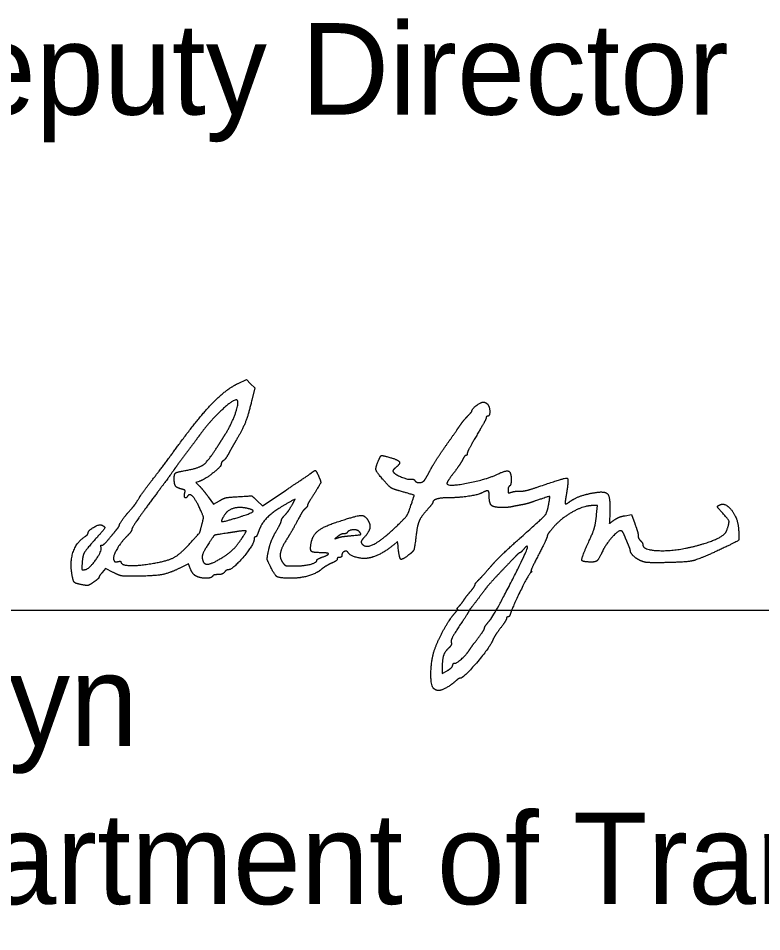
# Model space of a CAD drawing. Extents: x 0 to 68.9, y -26.1 to 22.
# Drawn here: x 25.975 to 27.114, y 8.446 to 9.844 of the extents above; entities that cross this region are included whole.
import ezdxf

# ---------------------------------------------------------------- set-up
doc = ezdxf.new("R2010")
doc.units = 0
doc.layers.add('SH_Data', color=7, linetype='Continuous')
doc.layers.add('SH_Text', color=7, linetype='Continuous')

msp = doc.modelspace()

# ---------------------------------------------------------------- linework, layer by layer
at = {"layer": 'SH_Data'}
msp.add_line((24.827, 8.9384), (28.327, 8.9384), dxfattribs=at)
at = {"layer": 'SH_Text'}
for points in [[(26.3123, 9.2855), (26.3249, 9.2913), (26.3313, 9.285), (26.3376, 9.2786), (26.3332, 9.2599)], [(26.2524, 9.1355), (26.2473, 9.1339), (26.2525, 9.1288)], [(26.3413, 9.1058), (26.3495, 9.0982), (26.3857, 9.1223)], [(26.2662, 9.1121), (26.2747, 9.1006), (26.2835, 9.1058)], [(26.3952, 9.1005), (26.3997, 9.1085), (26.3941, 9.1055)], [(26.8611, 9.0846), (26.8625, 9.0984), (26.8547, 9.0984)], [(26.9049, 9.083), (26.9146, 9.0846), (26.9196, 9.071)], [(26.557, 9.0369), (26.5563, 9.0437), (26.5504, 9.0386)], [(26.2393, 9.0013), (26.236, 9.0093), (26.2221, 9.0024)], [(26.1207, 8.9962), (26.1092, 9.002), (26.1042, 8.9962)], [(26.6247, 8.8507), (26.6247, 8.8414), (26.6322, 8.8457)]]:
    msp.add_lwpolyline(points, dxfattribs=at)
for points in [[(26.2227, 9.1936), (26.2524, 9.2342), (26.2942, 9.2771), (26.3123, 9.2855)], [(26.3108, 9.2597), (26.3072, 9.2633), (26.2686, 9.2276), (26.2532, 9.2063)], [(26.2925, 9.2076), (26.302, 9.2225), (26.3139, 9.2566), (26.3108, 9.2597)], [(26.3332, 9.2599), (26.3282, 9.2388), (26.3191, 9.2152), (26.3096, 9.1992)], [(26.6703, 9.2436), (26.6703, 9.2464), (26.6835, 9.2567), (26.6872, 9.2568)], [(26.6872, 9.2568), (26.6893, 9.2568), (26.6922, 9.2555), (26.6938, 9.254)], [(26.6637, 9.2355), (26.6673, 9.2391), (26.6703, 9.2427), (26.6703, 9.2436)], [(26.6938, 9.254), (26.6973, 9.2505), (26.6977, 9.2352), (26.6943, 9.2352)], [(26.6499, 9.2182), (26.6539, 9.2241), (26.6601, 9.2318), (26.6637, 9.2355)], [(26.6919, 9.2327), (26.6919, 9.2313), (26.6854, 9.2192), (26.6775, 9.2059)], [(26.6943, 9.2352), (26.693, 9.2352), (26.6919, 9.2341), (26.6919, 9.2327)], [(26.6283, 9.1872), (26.6362, 9.1985), (26.646, 9.2124), (26.6499, 9.2182)], [(26.2532, 9.2063), (26.2496, 9.2014), (26.2402, 9.1887), (26.2323, 9.1782)], [(26.282, 9.191), (26.2853, 9.1962), (26.29, 9.2037), (26.2925, 9.2076)], [(26.6775, 9.2059), (26.6696, 9.1925), (26.6631, 9.1801), (26.6631, 9.1784)], [(26.1826, 9.1402), (26.1914, 9.1515), (26.2095, 9.1756), (26.2227, 9.1936)], [(26.2322, 9.1523), (26.2528, 9.156), (26.2668, 9.167), (26.282, 9.191)], [(26.3096, 9.1992), (26.3061, 9.1933), (26.3009, 9.1841), (26.2981, 9.1788)], [(26.6069, 9.1536), (26.6107, 9.1609), (26.6204, 9.176), (26.6283, 9.1872)], [(26.2323, 9.1782), (26.2244, 9.1677), (26.2163, 9.1567), (26.2143, 9.1538)], [(26.2981, 9.1788), (26.2952, 9.1736), (26.2914, 9.1684), (26.2896, 9.1673)], [(26.5263, 9.1655), (26.53, 9.1745), (26.5331, 9.1756), (26.5458, 9.1718)], [(26.6611, 9.1752), (26.66, 9.1752), (26.6577, 9.1723), (26.6559, 9.1686)], [(26.6631, 9.1784), (26.6631, 9.1766), (26.6622, 9.1752), (26.6611, 9.1752)], [(26.2863, 9.1619), (26.2863, 9.1581), (26.2605, 9.1381), (26.2524, 9.1355)], [(26.2896, 9.1673), (26.2878, 9.1663), (26.2863, 9.1638), (26.2863, 9.1619)], [(26.5361, 9.136), (26.5245, 9.1491), (26.5223, 9.1559), (26.5263, 9.1655)], [(26.5458, 9.1718), (26.5578, 9.1683), (26.5607, 9.1621), (26.553, 9.1562)], [(26.6559, 9.1686), (26.6541, 9.165), (26.6479, 9.1559), (26.6423, 9.1484)], [(26.2143, 9.1538), (26.2123, 9.1508), (26.197, 9.1299), (26.1802, 9.1072)], [(26.2143, 9.1402), (26.2143, 9.147), (26.2184, 9.1498), (26.2322, 9.1523)], [(26.3857, 9.1223), (26.4056, 9.1356), (26.4232, 9.1475), (26.4248, 9.1488)], [(26.4248, 9.1488), (26.4294, 9.1526), (26.4317, 9.1517), (26.4347, 9.1451)], [(26.4347, 9.1451), (26.4391, 9.1355), (26.4382, 9.1314), (26.4279, 9.1155)], [(26.553, 9.1562), (26.5503, 9.1541), (26.5488, 9.1513), (26.5498, 9.15)], [(26.5498, 9.15), (26.5524, 9.1462), (26.5724, 9.138), (26.577, 9.1388)], [(26.5977, 9.1374), (26.5989, 9.1391), (26.6031, 9.1464), (26.6069, 9.1536)], [(26.6423, 9.1484), (26.6366, 9.141), (26.6319, 9.1337), (26.6319, 9.1324)], [(26.6319, 9.1324), (26.6319, 9.1271), (26.6915, 9.138), (26.7095, 9.1466)], [(26.7095, 9.1466), (26.7225, 9.1528), (26.7303, 9.1496), (26.7303, 9.1382)], [(26.161, 9.1108), (26.164, 9.1156), (26.1737, 9.1288), (26.1826, 9.1402)], [(26.2253, 9.1238), (26.2181, 9.1256), (26.2143, 9.1313), (26.2143, 9.1402)], [(26.5595, 9.1209), (26.5488, 9.124), (26.5438, 9.1272), (26.5361, 9.136)], [(26.577, 9.1388), (26.5792, 9.1392), (26.5818, 9.1383), (26.5826, 9.137)], [(26.5826, 9.137), (26.5848, 9.1335), (26.5948, 9.1338), (26.5977, 9.1374)], [(26.7303, 9.1382), (26.7303, 9.1337), (26.7292, 9.1293), (26.7279, 9.1284)], [(26.7727, 9.1275), (26.813, 9.1414), (26.8189, 9.1398), (26.8148, 9.1159)], [(26.2304, 9.1175), (26.2313, 9.1211), (26.2301, 9.1226), (26.2253, 9.1238)], [(26.2347, 9.1128), (26.2323, 9.1089), (26.2291, 9.1124), (26.2304, 9.1175)], [(26.2525, 9.1288), (26.2553, 9.126), (26.2615, 9.1185), (26.2662, 9.1121)], [(26.5763, 9.0972), (26.582, 9.114), (26.5816, 9.1146), (26.5595, 9.1209)], [(26.6853, 9.1178), (26.6797, 9.1148), (26.6495, 9.1104), (26.6346, 9.1104)], [(26.6967, 9.1131), (26.6967, 9.1204), (26.693, 9.1219), (26.6853, 9.1178)], [(26.7279, 9.1284), (26.7266, 9.1276), (26.7255, 9.1248), (26.7255, 9.1221)], [(26.7255, 9.1221), (26.7255, 9.1182), (26.7265, 9.1176), (26.7309, 9.119)], [(26.7309, 9.119), (26.7339, 9.12), (26.7397, 9.1206), (26.7439, 9.1205)], [(26.7439, 9.1205), (26.748, 9.1203), (26.761, 9.1235), (26.7727, 9.1275)], [(26.8208, 9.105), (26.828, 9.1101), (26.8463, 9.1164), (26.8599, 9.1186)], [(26.8599, 9.1186), (26.8746, 9.1209), (26.8822, 9.1104), (26.8814, 9.0892)], [(26.1447, 9.0889), (26.1513, 9.0962), (26.1556, 9.102), (26.161, 9.1108)], [(26.1802, 9.1072), (26.1634, 9.0846), (26.1496, 9.0644), (26.1495, 9.0624)], [(26.2535, 9.0942), (26.2473, 9.1078), (26.2376, 9.1175), (26.2347, 9.1128)], [(26.2835, 9.1058), (26.29, 9.1097), (26.2976, 9.1114), (26.3127, 9.1122)], [(26.3127, 9.1122), (26.333, 9.1134), (26.3332, 9.1134), (26.3413, 9.1058)], [(26.3941, 9.1055), (26.3707, 9.093), (26.348, 9.0723), (26.3439, 9.0599)], [(26.4279, 9.1155), (26.4226, 9.1074), (26.4183, 9.0998), (26.4183, 9.0987)], [(26.6103, 9.1033), (26.6103, 9.1024), (26.6061, 9.097), (26.601, 9.0912)], [(26.6346, 9.1104), (26.6231, 9.1104), (26.6103, 9.1067), (26.6103, 9.1033)], [(26.716, 9.0955), (26.7036, 9.0955), (26.6967, 9.1018), (26.6967, 9.1131)], [(26.7673, 9.1055), (26.7595, 9.1028), (26.7499, 9.1001), (26.7459, 9.0995)], [(26.7879, 9.1009), (26.79, 9.1124), (26.7883, 9.1128), (26.7673, 9.1055)], [(26.8148, 9.1159), (26.8135, 9.1083), (26.8128, 9.1017), (26.8132, 9.1012)], [(26.8132, 9.1012), (26.8137, 9.1007), (26.8171, 9.1024), (26.8208, 9.105)], [(26.1303, 9.0684), (26.1303, 9.0701), (26.1395, 9.0831), (26.1447, 9.0889)], [(26.2568, 9.0696), (26.2593, 9.0795), (26.259, 9.0817), (26.2535, 9.0942)], [(26.3245, 9.0945), (26.3137, 9.0967), (26.2963, 9.0916), (26.2919, 9.085)], [(26.3139, 9.081), (26.3331, 9.0869), (26.3371, 9.092), (26.3245, 9.0945)], [(26.3824, 9.0824), (26.3879, 9.0884), (26.3904, 9.092), (26.3952, 9.1005)], [(26.4148, 9.0937), (26.4128, 9.0921), (26.4097, 9.0879), (26.4079, 9.0844)], [(26.4183, 9.0987), (26.4183, 9.0975), (26.4167, 9.0953), (26.4148, 9.0937)], [(26.558, 9.0699), (26.5684, 9.0799), (26.5726, 9.0861), (26.5763, 9.0972)], [(26.601, 9.0912), (26.5925, 9.0817), (26.5868, 9.0692), (26.5852, 9.0564)], [(26.7327, 9.0969), (26.7294, 9.0961), (26.7219, 9.0955), (26.716, 9.0955)], [(26.7459, 9.0995), (26.742, 9.0988), (26.736, 9.0977), (26.7327, 9.0969)], [(26.7431, 9.0479), (26.7786, 9.0795), (26.7855, 9.0876), (26.7879, 9.1009)], [(26.8547, 9.0984), (26.842, 9.0984), (26.8083, 9.08), (26.7961, 9.0665)], [(26.8814, 9.0892), (26.8808, 9.0708), (26.8806, 9.0711), (26.8884, 9.0766)], [(27.0515, 9.0898), (27.0462, 9.0955), (27.046, 9.0981), (27.0506, 9.0999)], [(27.0506, 9.0999), (27.0592, 9.1032), (27.0776, 9.0783), (27.0786, 9.062)], [(27.0606, 9.0607), (27.0646, 9.0725), (27.0631, 9.0774), (27.0515, 9.0898)], [(26.2919, 9.085), (26.2849, 9.0743), (26.2895, 9.0735), (26.3139, 9.081)], [(26.37, 9.0583), (26.3744, 9.066), (26.3782, 9.0736), (26.3784, 9.0754)], [(26.3784, 9.0754), (26.3787, 9.0771), (26.3805, 9.0803), (26.3824, 9.0824)], [(26.4079, 9.0844), (26.3997, 9.069), (26.392, 9.0552), (26.3858, 9.0455)], [(26.4617, 9.0727), (26.4935, 9.0833), (26.507, 9.0837), (26.512, 9.0742)], [(26.512, 9.0742), (26.5152, 9.0682), (26.5118, 9.0568), (26.5044, 9.0489)], [(26.8464, 9.0368), (26.8554, 9.0567), (26.8595, 9.0699), (26.8611, 9.0846)], [(26.8884, 9.0766), (26.8921, 9.0793), (26.8996, 9.0822), (26.9049, 9.083)], [(26.0823, 9.0564), (26.0824, 9.0602), (26.0991, 9.0701), (26.1029, 9.0687)], [(26.1029, 9.0687), (26.1089, 9.0664), (26.1066, 9.0615), (26.0923, 9.0456)], [(26.1158, 9.0492), (26.1211, 9.0558), (26.1266, 9.0625), (26.1279, 9.0641)], [(26.1279, 9.0641), (26.1292, 9.0657), (26.1303, 9.0677), (26.1303, 9.0684)], [(26.1495, 9.0624), (26.1494, 9.0605), (26.1461, 9.0556), (26.1421, 9.0517)], [(26.2371, 9.0391), (26.2532, 9.0567), (26.2535, 9.0572), (26.2568, 9.0696)], [(26.4241, 9.0416), (26.4262, 9.0529), (26.4424, 9.0663), (26.4617, 9.0727)], [(26.4978, 9.0585), (26.495, 9.0618), (26.4816, 9.061), (26.4793, 9.0574)], [(26.501, 9.041), (26.5064, 9.0324), (26.5331, 9.0459), (26.558, 9.0699)], [(26.7961, 9.0665), (26.7903, 9.06), (26.7855, 9.0534), (26.7855, 9.0519)], [(26.9196, 9.071), (26.9224, 9.0636), (26.9247, 9.0554), (26.9247, 9.0529)], [(27.0118, 9.0364), (27.0354, 9.0427), (27.0584, 9.0541), (27.0606, 9.0607)], [(27.0786, 9.062), (27.0796, 9.0467), (27.0769, 9.0436), (27.0535, 9.0326)], [(26.0575, 8.9948), (26.0545, 9.0133), (26.0653, 9.0433), (26.0777, 9.0511)], [(26.0777, 9.0511), (26.0802, 9.0527), (26.0823, 9.0551), (26.0823, 9.0564)], [(26.1035, 9.0379), (26.1049, 9.0376), (26.1104, 9.0426), (26.1158, 9.0492)], [(26.1421, 9.0517), (26.1323, 9.0421), (26.1199, 9.02), (26.1217, 9.0153)], [(26.2947, 9.0562), (26.2769, 9.0536), (26.2749, 9.0525), (26.2676, 9.0413)], [(26.2872, 9.0185), (26.2984, 9.0255), (26.3094, 9.036), (26.3171, 9.0472)], [(26.3121, 9.0589), (26.3065, 9.058), (26.2987, 9.0568), (26.2947, 9.0562)], [(26.3367, 9.0474), (26.3365, 9.0389), (26.3034, 9), (26.2963, 9)], [(26.3171, 9.0472), (26.3249, 9.0586), (26.324, 9.0607), (26.3121, 9.0589)], [(26.3387, 9.0504), (26.3376, 9.0504), (26.3367, 9.0491), (26.3367, 9.0474)], [(26.3439, 9.0599), (26.3421, 9.0547), (26.3398, 9.0504), (26.3387, 9.0504)], [(26.359, 9.0305), (26.3606, 9.0381), (26.3655, 9.0507), (26.37, 9.0583)], [(26.465, 9.0514), (26.4604, 9.0477), (26.4604, 9.0477), (26.4651, 9.0493)], [(26.4738, 9.0552), (26.4715, 9.0552), (26.4675, 9.0535), (26.465, 9.0514)], [(26.4651, 9.0493), (26.4678, 9.0503), (26.4753, 9.0515), (26.4819, 9.0521)], [(26.4793, 9.0574), (26.4786, 9.0562), (26.4761, 9.0552), (26.4738, 9.0552)], [(26.4819, 9.0521), (26.4986, 9.0536), (26.501, 9.0546), (26.4978, 9.0585)], [(26.5044, 9.0489), (26.5017, 9.046), (26.5001, 9.0424), (26.501, 9.041)], [(26.5852, 9.0564), (26.5823, 9.0339), (26.5806, 9.0284), (26.5749, 9.024)], [(26.699, 9.0052), (26.7062, 9.0136), (26.7261, 9.0328), (26.7431, 9.0479)], [(26.7855, 9.0519), (26.7855, 9.0503), (26.7796, 9.0374), (26.7723, 9.0233)], [(26.8979, 9.06), (26.8936, 9.06), (26.8754, 9.0395), (26.8706, 9.0294)], [(26.9035, 9.0534), (26.902, 9.0571), (26.8995, 9.06), (26.8979, 9.06)], [(26.9094, 9.0393), (26.9077, 9.0434), (26.905, 9.0498), (26.9035, 9.0534)], [(26.9247, 9.0529), (26.9247, 9.0504), (26.9263, 9.0468), (26.9283, 9.0448)], [(26.0923, 9.0456), (26.0786, 9.0304), (26.0736, 9.0203), (26.073, 9.0065)], [(26.0779, 9.0005), (26.0842, 9.0014), (26.1043, 9.0298), (26.1023, 9.035)], [(26.1023, 9.035), (26.1015, 9.037), (26.1021, 9.0383), (26.1035, 9.0379)], [(26.1806, 9.0098), (26.2033, 9.0135), (26.223, 9.0237), (26.2371, 9.0391)], [(26.2676, 9.0413), (26.2594, 9.0286), (26.2562, 9.0188), (26.2585, 9.013)], [(26.3858, 9.0455), (26.3779, 9.0329), (26.3756, 9.0177), (26.3807, 9.0109)], [(26.4377, 9.0264), (26.4261, 9.0264), (26.4221, 9.031), (26.4241, 9.0416)], [(26.5504, 9.0386), (26.5411, 9.0304), (26.521, 9.0198), (26.5119, 9.0181)], [(26.5749, 9.024), (26.5632, 9.0148), (26.5588, 9.0179), (26.557, 9.0369)], [(26.6964, 8.9214), (26.7041, 8.9301), (26.7573, 9.0338), (26.7552, 9.0359)], [(26.7552, 9.0359), (26.7545, 9.0366), (26.7519, 9.0348), (26.7495, 9.0318)], [(26.8537, 9.012), (26.8392, 9.012), (26.8376, 9.0175), (26.8464, 9.0368)], [(26.9128, 9.0297), (26.9127, 9.0308), (26.9112, 9.0351), (26.9094, 9.0393)], [(26.9283, 9.0448), (26.9303, 9.0428), (26.9319, 9.0401), (26.9319, 9.0388)], [(26.9319, 9.0388), (26.9319, 9.0302), (26.9825, 9.0288), (27.0118, 9.0364)], [(27.0535, 9.0326), (27.0187, 9.0163), (26.9977, 9.0115), (26.9583, 9.011)], [(26.2585, 9.013), (26.2605, 9.0077), (26.2741, 9.0103), (26.2872, 9.0185)], [(26.361, 9.0065), (26.3566, 9.0156), (26.3564, 9.0178), (26.359, 9.0305)], [(26.4327, 9.0147), (26.4327, 9.0157), (26.4364, 9.0179), (26.441, 9.0195)], [(26.441, 9.0195), (26.4513, 9.0232), (26.4497, 9.0264), (26.4377, 9.0264)], [(26.4675, 9.0192), (26.4655, 9.0192), (26.4639, 9.0181), (26.4639, 9.0168)], [(26.4711, 9.0226), (26.4711, 9.0207), (26.4695, 9.0192), (26.4675, 9.0192)], [(26.4806, 9.0266), (26.4786, 9.0299), (26.4711, 9.0267), (26.4711, 9.0226)], [(26.5119, 9.0181), (26.5033, 9.0165), (26.4835, 9.0219), (26.4806, 9.0266)], [(26.7349, 9.0186), (26.7309, 9.0143), (26.7203, 9.0033), (26.7115, 8.994)], [(26.7437, 9.0264), (26.743, 9.0264), (26.739, 9.0229), (26.7349, 9.0186)], [(26.7495, 9.0318), (26.7471, 9.0289), (26.7445, 9.0264), (26.7437, 9.0264)], [(26.7723, 9.0233), (26.765, 9.0092), (26.7599, 8.9976), (26.7609, 8.9976)], [(26.8706, 9.0294), (26.8649, 9.017), (26.8601, 9.012), (26.8537, 9.012)], [(26.9285, 9.0141), (26.9214, 9.0174), (26.9129, 9.0258), (26.9128, 9.0297)], [(26.073, 9.0065), (26.0728, 9.0009), (26.0736, 8.9998), (26.0779, 9.0005)], [(26.1217, 9.0153), (26.1226, 9.0129), (26.1249, 9.012), (26.1279, 9.0127)], [(26.1279, 9.0127), (26.1306, 9.0134), (26.1327, 9.0131), (26.1327, 9.012)], [(26.1327, 9.012), (26.1327, 9.0074), (26.1584, 9.0062), (26.1806, 9.0098)], [(26.3928, 8.9873), (26.3753, 8.9874), (26.3683, 8.9916), (26.361, 9.0065)], [(26.3807, 9.0109), (26.3836, 9.007), (26.3871, 9.0061), (26.3983, 9.0061)], [(26.3983, 9.0061), (26.4123, 9.006), (26.4327, 9.0111), (26.4327, 9.0147)], [(26.4585, 9.0119), (26.4512, 9.0086), (26.4435, 9.004), (26.4393, 9.0005)], [(26.4639, 9.0168), (26.4639, 9.0154), (26.4615, 9.0132), (26.4585, 9.0119)], [(26.6806, 8.9848), (26.6835, 8.9876), (26.6918, 8.9968), (26.699, 9.0052)], [(26.9583, 9.011), (26.9434, 9.0109), (26.9331, 9.0119), (26.9285, 9.0141)], [(26.074, 8.9771), (26.0631, 8.9791), (26.0593, 8.9832), (26.0575, 8.9948)], [(26.1042, 8.9962), (26.1014, 8.993), (26.0991, 8.9896), (26.0991, 8.9886)], [(26.1515, 8.9904), (26.1359, 8.9904), (26.13, 8.9915), (26.1207, 8.9962)], [(26.2221, 9.0024), (26.2066, 8.9947), (26.1814, 8.9904), (26.1515, 8.9904)], [(26.2475, 8.9906), (26.2449, 8.9921), (26.2412, 8.9968), (26.2393, 9.0013)], [(26.2731, 8.9904), (26.2711, 8.9872), (26.2536, 8.9874), (26.2475, 8.9906)], [(26.2814, 8.9928), (26.2776, 8.9928), (26.2739, 8.9918), (26.2731, 8.9904)], [(26.2911, 8.9964), (26.2895, 8.9945), (26.2851, 8.9928), (26.2814, 8.9928)], [(26.2963, 9), (26.2951, 9), (26.2928, 8.9984), (26.2911, 8.9964)], [(26.4393, 9.0005), (26.4316, 8.9942), (26.4073, 8.9872), (26.3928, 8.9873)], [(26.7115, 8.994), (26.7027, 8.9847), (26.6928, 8.9735), (26.6895, 8.969)], [(26.7601, 8.9958), (26.7574, 8.994), (26.7322, 8.943), (26.7293, 8.9334)], [(26.7609, 8.9976), (26.7619, 8.9976), (26.7615, 8.9968), (26.7601, 8.9958)], [(26.0907, 8.9812), (26.0842, 8.9767), (26.0806, 8.9758), (26.074, 8.9771)], [(26.0991, 8.9886), (26.0991, 8.9876), (26.0953, 8.9843), (26.0907, 8.9812)], [(26.6685, 8.9677), (26.6721, 8.972), (26.6751, 8.9764), (26.6752, 8.9776)], [(26.6752, 8.9776), (26.6752, 8.9787), (26.6776, 8.9819), (26.6806, 8.9848)], [(26.6583, 8.9544), (26.6603, 8.9575), (26.6649, 8.9635), (26.6685, 8.9677)], [(26.6895, 8.969), (26.6814, 8.9581), (26.6709, 8.9443), (26.6679, 8.9407)], [(26.6505, 8.9444), (26.6528, 8.9469), (26.6563, 8.9514), (26.6583, 8.9544)], [(26.6145, 8.882), (26.6204, 8.8969), (26.6375, 8.9268), (26.6447, 8.9346)], [(26.6447, 8.9346), (26.6473, 8.9376), (26.6488, 8.94), (26.6479, 8.94)], [(26.6479, 8.94), (26.647, 8.94), (26.6482, 8.942), (26.6505, 8.9444)], [(26.6655, 8.9368), (26.6655, 8.9363), (26.6592, 8.9264), (26.6514, 8.9147)], [(26.6679, 8.9407), (26.6666, 8.9391), (26.6655, 8.9374), (26.6655, 8.9368)], [(26.6895, 8.9111), (26.6895, 8.9124), (26.6926, 8.917), (26.6964, 8.9214)], [(26.7231, 8.9255), (26.7231, 8.9242), (26.7188, 8.9174), (26.7136, 8.9105)], [(26.7253, 8.928), (26.7241, 8.928), (26.7231, 8.9269), (26.7231, 8.9255)], [(26.7293, 8.9334), (26.7283, 8.9305), (26.7266, 8.928), (26.7253, 8.928)], [(26.6514, 8.9147), (26.6428, 8.9017), (26.6378, 8.8919), (26.6385, 8.8892)], [(26.6793, 8.8952), (26.6849, 8.9026), (26.6895, 8.9097), (26.6895, 8.9111)], [(26.7136, 8.9105), (26.7084, 8.9036), (26.7033, 8.8956), (26.7022, 8.8928)], [(26.7022, 8.8928), (26.6986, 8.8829), (26.6574, 8.8344), (26.6527, 8.8344)], [(26.6667, 8.878), (26.668, 8.8801), (26.6737, 8.8879), (26.6793, 8.8952)], [(26.6127, 8.8176), (26.6068, 8.8214), (26.608, 8.8657), (26.6145, 8.882)], [(26.6349, 8.8806), (26.6289, 8.8754), (26.6247, 8.8631), (26.6247, 8.8507)], [(26.6385, 8.8892), (26.6392, 8.8867), (26.6376, 8.8831), (26.6349, 8.8806)], [(26.6439, 8.8572), (26.6458, 8.856), (26.6625, 8.8712), (26.6667, 8.878)], [(26.6322, 8.8457), (26.6364, 8.8481), (26.6403, 8.8519), (26.6409, 8.8542)], [(26.6409, 8.8542), (26.6415, 8.8565), (26.6429, 8.8579), (26.6439, 8.8572)], [(26.6453, 8.8299), (26.6391, 8.8242), (26.6231, 8.8152), (26.6192, 8.8153)], [(26.6527, 8.8344), (26.6514, 8.8344), (26.648, 8.8324), (26.6453, 8.8299)], [(26.6192, 8.8153), (26.6176, 8.8153), (26.6147, 8.8163), (26.6127, 8.8176)]]:
    msp.add_open_spline(points, degree=2, dxfattribs=at)

# ---------------------------------------------------------------- texts
for s, p in [('District       Deputy Director', (24.827, 9.6969)), ('Pamela Boratyn', (24.827, 8.7303)), ('Director, Department of Transportation', (24.827, 8.4884))]:
    msp.add_text(s, height=0.14, dxfattribs=at).set_placement(p)

doc.saveas('drawing.dxf')
